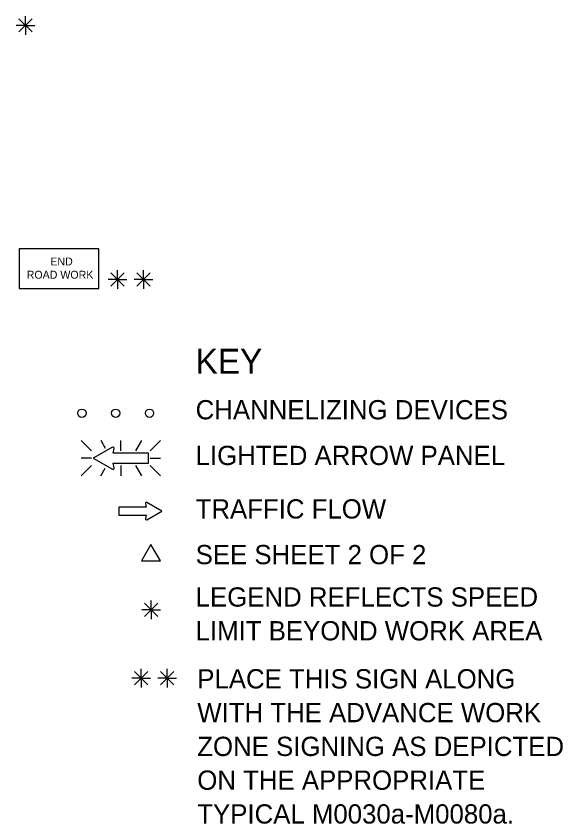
# Model space of a CAD drawing. Extents: x 16335 to 18464, y 5417 to 6974.
# Drawn here: x 17163.7 to 17427.4, y 6527.3 to 6917.1 of the extents above; entities that cross this region are included whole.
import ezdxf

# ---------------------------------------------------------------- set-up
doc = ezdxf.new("R2010")
doc.units = 0
for name, color, linetype in [('MT_SCRATCH_LEVEL_E', 7, 'Continuous'), ('TRAFFIC_SIGNS_PR', 7, 'Continuous'), ('TYPICAL_TEXT_DIMEN_EX', 7, 'Continuous'), ('TYPICAL_TEXT_DIMEN_PR', 7, 'Continuous')]:
    doc.layers.add(name, color=color, linetype=linetype)

msp = doc.modelspace()

# ---------------------------------------------------------------- linework, layer by layer
at = {"layer": 'MT_SCRATCH_LEVEL_E'}
for p, q in [((17226.09, 6681.88), (17226.41, 6680.1)), ((17234.02, 6678.25), (17226.77, 6682.36)), ((17226.41, 6680.1), (17213.15, 6680.1)), ((17213.15, 6680.1), (17213.15, 6676.36)), ((17213.15, 6676.36), (17226.41, 6676.36)), ((17226.41, 6676.36), (17226.09, 6674.58)), ((17226.77, 6674.1), (17234.02, 6678.25))]:
    msp.add_line(p, q, dxfattribs=at)
for centre, start, end in [((17226.55, 6681.95), 60.4248, 189.9638), ((17226.55, 6674.51), 170.0362, 299.7731)]:
    msp.add_arc(centre, 0.463, start, end, dxfattribs=at)
at = {"layer": 'TRAFFIC_SIGNS_PR'}
for p, q in [((17195.08, 6712.26), (17200.01, 6707.33)), ((17206.84, 6708.44), (17204.64, 6712.26)), ((17214.16, 6707.33), (17214.16, 6712.26)), ((17221.4, 6707.33), (17224.25, 6712.26)), ((17228.31, 6707.33), (17233.25, 6712.26)), ((17200.01, 6703.77), (17195.08, 6703.77)), ((17228.31, 6703.77), (17233.25, 6703.77)), ((17195.08, 6695.28), (17200.01, 6700.21)), ((17214.16, 6700.21), (17214.16, 6695.28)), ((17224.29, 6695.28), (17221.44, 6700.21)), ((17228.31, 6700.21), (17233.25, 6695.28)), ((17204.59, 6695.28), (17206.71, 6698.94))]:
    msp.add_line(p, q, dxfattribs=at)
msp.add_lwpolyline([(17165.18, 6785.64), (17203.58, 6785.64), (17203.58, 6804.84), (17165.18, 6804.84)], close=True, dxfattribs=at)
for points in [[(17210.09, 6709.05), (17200.8, 6703.77), (17210.09, 6698.45)], [(17210.97, 6699.08), (17210.57, 6701.35), (17227.58, 6701.35), (17227.58, 6706.15), (17210.57, 6706.15), (17210.97, 6708.43)]]:
    msp.add_lwpolyline(points, dxfattribs=at)
for centre in [(17195.42, 6725.46), (17211.72, 6725.46), (17228.02, 6725.46)]:
    msp.add_circle(centre, 2, dxfattribs=at)
for centre, radius, start, end in [((17210.38, 6708.52), 0.598, 350.7308, 118.8916), ((17210.38, 6698.97), 0.597, 241.4833, 9.9593)]:
    msp.add_arc(centre, radius, start, end, dxfattribs=at)
at = {"layer": 'TYPICAL_TEXT_DIMEN_PR'}
for p, q in [((17165.05, 6915.81), (17171.43, 6909.43)), ((17171.43, 6915.81), (17165.05, 6909.43)), ((17168.24, 6912.62), (17168.24, 6917.07)), ((17168.24, 6912.62), (17163.71, 6912.62)), ((17168.24, 6912.62), (17171.43, 6912.62)), ((17168.24, 6912.62), (17172.72, 6912.62)), ((17168.24, 6912.62), (17168.24, 6908.12)), ((17215.79, 6793.2), (17209.41, 6786.82)), ((17209.42, 6793.2), (17215.79, 6786.82)), ((17212.6, 6790.01), (17212.6, 6794.47)), ((17221.97, 6793.2), (17228.35, 6786.82)), ((17228.35, 6793.2), (17221.97, 6786.82)), ((17225.16, 6790.01), (17225.16, 6794.47)), ((17212.6, 6790.01), (17208.07, 6790.01)), ((17212.6, 6790.01), (17215.79, 6790.01)), ((17212.6, 6790.01), (17217.08, 6790.01)), ((17212.6, 6790.01), (17212.6, 6785.51)), ((17225.16, 6790.01), (17220.63, 6790.01)), ((17225.16, 6790.01), (17228.35, 6790.01)), ((17225.16, 6790.01), (17229.64, 6790.01)), ((17225.16, 6790.01), (17225.16, 6785.51)), ((17232, 6633.82), (17225.62, 6627.44)), ((17225.63, 6633.82), (17232, 6627.44)), ((17228.81, 6630.63), (17228.81, 6635.09)), ((17228.81, 6630.63), (17224.28, 6630.63)), ((17228.81, 6630.63), (17232, 6630.63)), ((17228.81, 6630.63), (17233.29, 6630.63)), ((17228.81, 6630.63), (17228.81, 6626.13)), ((17220.79, 6600.82), (17227.16, 6594.44)), ((17227.16, 6600.82), (17220.79, 6594.44)), ((17223.98, 6597.63), (17223.98, 6602.09)), ((17233.34, 6600.82), (17239.72, 6594.44)), ((17239.72, 6600.82), (17233.34, 6594.44)), ((17236.53, 6597.63), (17236.53, 6602.09)), ((17223.98, 6597.63), (17219.44, 6597.63)), ((17223.98, 6597.63), (17227.16, 6597.63)), ((17223.98, 6597.63), (17228.45, 6597.63)), ((17223.98, 6597.63), (17223.98, 6593.13)), ((17236.53, 6597.63), (17232, 6597.63)), ((17236.53, 6597.63), (17239.72, 6597.63)), ((17236.53, 6597.63), (17241.01, 6597.63)), ((17236.53, 6597.63), (17236.53, 6593.13))]:
    msp.add_line(p, q, dxfattribs=at)
msp.add_lwpolyline([(17228.73, 6662.08), (17224.2, 6654.24), (17233.25, 6654.24)], close=True, dxfattribs=at)

# ---------------------------------------------------------------- texts
at = {"layer": 'TRAFFIC_SIGNS_PR'}
for s, p in [('END', (17180.18, 6796.77)), ('ROAD WORK', (17168.79, 6790.38))]:
    msp.add_text(s, height=3.831, dxfattribs=at).set_placement(p)
at = {"layer": 'TYPICAL_TEXT_DIMEN_EX'}
for s, height, p in [('KEY', 12, (17250.27, 6744.56)), ('CHANNELIZING DEVICES', 9.3, (17250.27, 6722.51)), ('LIGHTED ARROW PANEL', 9.3, (17250.27, 6700.46)), ('TRAFFIC FLOW', 9.3, (17250.27, 6674.66)), ('SEE SHEET 2 OF 2', 9.3, (17250.27, 6652.61)), ('LEGEND REFLECTS SPEED', 9.3, (17250.27, 6632.16)), ('LIMIT BEYOND WORK AREA', 9.3, (17250.27, 6615.86)), ('PLACE THIS SIGN ALONG', 9.3, (17251.06, 6592.67)), ('WITH THE ADVANCE WORK', 9.3, (17251.06, 6576.37)), ('ZONE SIGNING AS DEPICTED', 9.3, (17251.06, 6560.07)), ('ON THE APPROPRIATE', 9.3, (17251.06, 6543.77)), ('TYPICAL M0030a-M0080a.', 9.3, (17251.06, 6527.47))]:
    msp.add_text(s, height=height, dxfattribs=at).set_placement(p)

doc.saveas('drawing.dxf')
